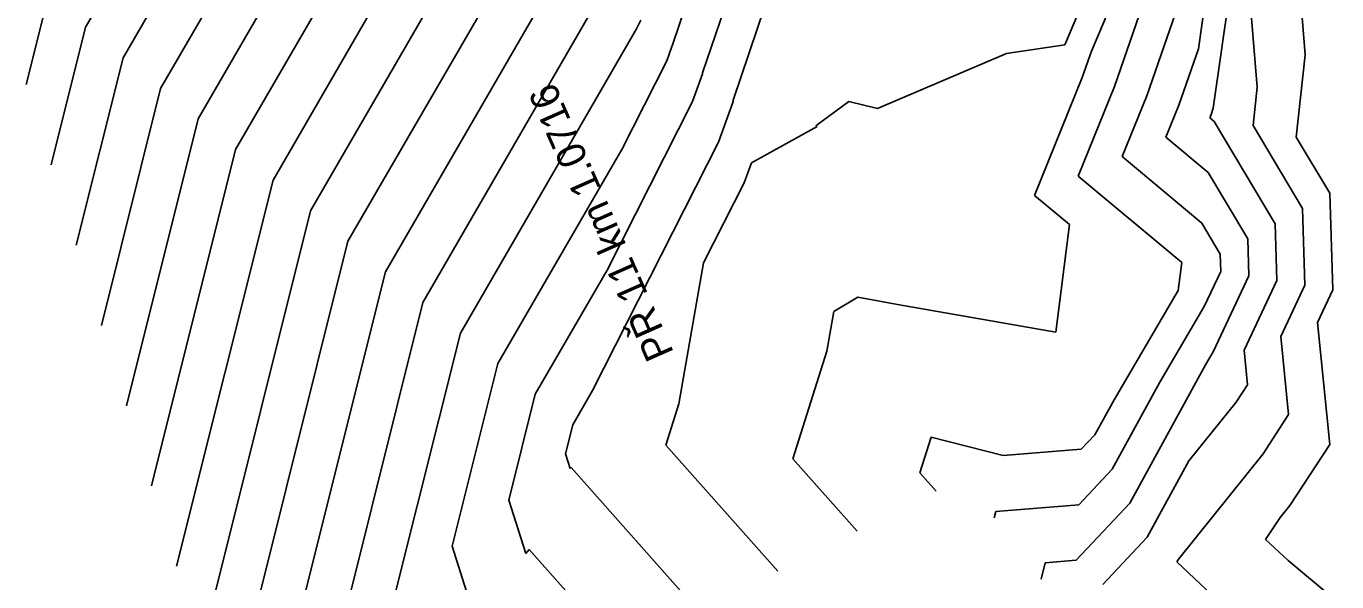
# Model space of a CAD drawing. Extents: x -549394 to -546608, y -1037055 to -1033629.
# Drawn here: x -547337.7 to -546924.3, y -1036782.7 to -1036607.7 of the extents above; entities that cross this region are included whole.
import ezdxf

# ---------------------------------------------------------------- set-up
doc = ezdxf.new("R2010")
doc.units = 0
for name, color, linetype in [('hlavni_vrst', 7, 'Continuous'), ('norm_vrst', 7, 'Continuous'), ('x_popis_pricne_rezy_C31', 7, 'Continuous')]:
    doc.layers.add(name, color=color, linetype=linetype)

msp = doc.modelspace()

# ---------------------------------------------------------------- linework, layer by layer
at = {"layer": 'hlavni_vrst'}
for p, q in [((-547307.11, -1036617.61), (-547290.03, -1036588.14)), ((-546994.44, -1036626.7), (-546982.33, -1036591.7)), ((-546934.27, -1036616.63), (-546936.34, -1036592.46)), ((-547248.03, -1036665.8), (-547208.29, -1036597.26)), ((-547134, -1036613.83), (-547129.38, -1036600.2)), ((-547135.66, -1036618.58), (-547134.01, -1036614.01)), ((-547134.01, -1036614.01), (-547134, -1036613.83)), ((-547321.87, -1036676.65), (-547307.11, -1036617.61)), ((-547149.83, -1036646.52), (-547135.66, -1036618.58)), ((-546937.13, -1036642.58), (-546934.27, -1036616.63)), ((-547005.86, -1036654.86), (-546994.44, -1036626.7)), ((-546926.57, -1036660.32), (-546937.13, -1036642.58)), ((-547188.94, -1036714), (-547149.83, -1036646.52)), ((-546973.19, -1036682.1), (-547005.86, -1036654.86)), ((-546925.59, -1036690.71), (-546926.57, -1036660.32)), ((-547282.37, -1036803.14), (-547248.03, -1036665.8)), ((-546974.33, -1036690.95), (-546973.19, -1036682.1)), ((-546994.58, -1036725.38), (-546974.33, -1036690.95)), ((-546930.45, -1036701.02), (-546925.59, -1036690.71)), ((-546926.57, -1036739.43), (-546930.45, -1036701.02)), ((-547203.33, -1036771.52), (-547188.94, -1036714)), ((-547000.65, -1036736.43), (-546994.58, -1036725.38)), ((-547055.8, -1036748.38), (-547052.27, -1036737.18)), ((-547052.27, -1036737.18), (-547029.57, -1036742.95)), ((-547004.93, -1036741), (-547000.65, -1036736.43)), ((-547029.57, -1036742.95), (-547004.93, -1036741)), ((-546939.15, -1036758.68), (-546926.57, -1036739.43)), ((-547050.66, -1036754.16), (-547055.8, -1036748.38)), ((-546942.21, -1036762.49), (-546939.15, -1036758.68)), ((-546946.78, -1036769.4), (-546942.21, -1036762.49)), ((-547194.12, -1036800.51), (-547203.33, -1036771.52)), ((-546939.65, -1036776.06), (-546946.78, -1036769.4)), ((-546916.57, -1036795.26), (-546939.65, -1036776.06))]:
    msp.add_line(p, q, dxfattribs=at)
at = {"layer": 'norm_vrst'}
for p, q in [((-547010.16, -1036613.49), (-546995.25, -1036578.44)), ((-547001.73, -1036615.51), (-546986.91, -1036580.65)), ((-547318.93, -1036607.97), (-547306.38, -1036586.32)), ((-547295.29, -1036627.25), (-547273.68, -1036589.97)), ((-546967.98, -1036614.76), (-546963.87, -1036586.17)), ((-546963.31, -1036633.53), (-546956.72, -1036587.72)), ((-547283.48, -1036636.89), (-547257.33, -1036591.79)), ((-547271.66, -1036646.53), (-547240.99, -1036593.61)), ((-547337.68, -1036626.05), (-547330.74, -1036598.33)), ((-547259.84, -1036656.17), (-547224.64, -1036595.44)), ((-547124.36, -1036622.38), (-547115.59, -1036596.46)), ((-546984.28, -1036629.61), (-546972.65, -1036595.99)), ((-547236.21, -1036675.44), (-547191.94, -1036599.08)), ((-547224.39, -1036685.08), (-547175.6, -1036600.9)), ((-547114.72, -1036630.92), (-547104.53, -1036600.82)), ((-546949.42, -1036626.82), (-546951.49, -1036602.61)), ((-547212.58, -1036694.72), (-547159.25, -1036602.73)), ((-547145.21, -1036608.53), (-547143.8, -1036605.76)), ((-547329.77, -1036651.35), (-547318.93, -1036607.97)), ((-547200.76, -1036704.36), (-547145.21, -1036608.53)), ((-547028.47, -1036616.27), (-547010.16, -1036613.49)), ((-546974.13, -1036632.52), (-546967.98, -1036614.76)), ((-547069.17, -1036633.54), (-547028.47, -1036616.27)), ((-547004.6, -1036623.79), (-547001.73, -1036615.51)), ((-547127.52, -1036631.39), (-547124.37, -1036622.71)), ((-547124.37, -1036622.71), (-547124.36, -1036622.38)), ((-547313.97, -1036701.95), (-547295.29, -1036627.25)), ((-547019.68, -1036660.98), (-547004.6, -1036623.79)), ((-546950.76, -1036638.96), (-546949.42, -1036626.82)), ((-547154.45, -1036684.51), (-547127.52, -1036631.39)), ((-547119.37, -1036644.21), (-547114.74, -1036631.41)), ((-547114.74, -1036631.41), (-547114.72, -1036630.92)), ((-547088.63, -1036639.03), (-547078.28, -1036631.42)), ((-547078.28, -1036631.42), (-547069.17, -1036633.54)), ((-546992.05, -1036648.75), (-546984.28, -1036629.61)), ((-546978.23, -1036642.63), (-546974.13, -1036632.52)), ((-546964.41, -1036636.51), (-546963.97, -1036635.43)), ((-546963.97, -1036635.43), (-546963.31, -1036633.53)), ((-547306.07, -1036727.25), (-547283.48, -1036636.89)), ((-547108.94, -1036650.7), (-547088.21, -1036639.28)), ((-547088.21, -1036639.28), (-547088.63, -1036639.03)), ((-546962.98, -1036637.7), (-546964.41, -1036636.51)), ((-546943.82, -1036669.9), (-546962.98, -1036637.7)), ((-546935.2, -1036665.11), (-546950.76, -1036638.96)), ((-546964.93, -1036653.71), (-546978.23, -1036642.63)), ((-547298.17, -1036752.54), (-547271.66, -1036646.53)), ((-547159.06, -1036722.5), (-547119.37, -1036644.21)), ((-547111.23, -1036657.03), (-547108.94, -1036650.7)), ((-546966.88, -1036669.72), (-546992.05, -1036648.75)), ((-547290.27, -1036777.84), (-547259.84, -1036656.17)), ((-546952.45, -1036674.69), (-546964.93, -1036653.71)), ((-547124.03, -1036682.27), (-547111.23, -1036657.03)), ((-547008.65, -1036670.18), (-547019.68, -1036660.98)), ((-546934.42, -1036689.26), (-546935.2, -1036665.11)), ((-547013, -1036704.05), (-547008.65, -1036670.18)), ((-546961.08, -1036679.48), (-546966.88, -1036669.72)), ((-546943.25, -1036687.81), (-546943.82, -1036669.9)), ((-547274.47, -1036828.44), (-547236.21, -1036675.44)), ((-546952.07, -1036686.36), (-546952.45, -1036674.69)), ((-546960.9, -1036684.91), (-546961.08, -1036679.48)), ((-547256.91, -1036815.11), (-547224.39, -1036685.08)), ((-547177.13, -1036723.64), (-547154.45, -1036684.51)), ((-547131.88, -1036726.67), (-547124.03, -1036682.27)), ((-546966.13, -1036696.03), (-546960.9, -1036684.91)), ((-546963.31, -1036710.25), (-546952.07, -1036686.36)), ((-546953.58, -1036709.78), (-546943.25, -1036687.81)), ((-546942.01, -1036705.4), (-546934.42, -1036689.26)), ((-547082.98, -1036697.51), (-547075.38, -1036693.06)), ((-547075.38, -1036693.06), (-547062.87, -1036695.33)), ((-547239.05, -1036800.58), (-547212.58, -1036694.72)), ((-547085.21, -1036710.11), (-547082.98, -1036697.51)), ((-547062.87, -1036695.33), (-547013, -1036704.05)), ((-546980.16, -1036719.88), (-546966.13, -1036696.03)), ((-547221.19, -1036786.05), (-547200.76, -1036704.36)), ((-546939.53, -1036730.04), (-546942.01, -1036705.4)), ((-547095.88, -1036744.02), (-547085.21, -1036710.11)), ((-546952.48, -1036720.66), (-546953.58, -1036709.78)), ((-546965.75, -1036714.39), (-546963.31, -1036710.25)), ((-546989.66, -1036757.97), (-546965.75, -1036714.39)), ((-547165.31, -1036733.28), (-547159.06, -1036722.5)), ((-546995.15, -1036747.2), (-546980.16, -1036719.88)), ((-546956.05, -1036726.11), (-546952.48, -1036720.66)), ((-547185.47, -1036756.99), (-547177.13, -1036723.64)), ((-546970.96, -1036744.66), (-546956.05, -1036726.11)), ((-547135.97, -1036739.65), (-547131.88, -1036726.67)), ((-546947.6, -1036742.39), (-546939.53, -1036730.04)), ((-547167.61, -1036742.46), (-547165.31, -1036733.28)), ((-547166.14, -1036747.09), (-547167.61, -1036742.46)), ((-547100.59, -1036779.43), (-547135.97, -1036739.65)), ((-546974.18, -1036775.46), (-546947.6, -1036742.39)), ((-547165.85, -1036746.75), (-547166.14, -1036747.09)), ((-547125.55, -1036792.06), (-547165.85, -1036746.75)), ((-547075.62, -1036766.8), (-547095.88, -1036744.02)), ((-547005.73, -1036758.48), (-546995.15, -1036747.2)), ((-546984.17, -1036768.73), (-546970.96, -1036744.66)), ((-547180.13, -1036773.8), (-547185.47, -1036756.99)), ((-547031.9, -1036760.56), (-547005.73, -1036758.48)), ((-547006.54, -1036775.97), (-546989.66, -1036757.97)), ((-547032.39, -1036762.59), (-547031.9, -1036760.56)), ((-546998.11, -1036783.6), (-546984.17, -1036768.73)), ((-547179.1, -1036772.55), (-547180.13, -1036773.8)), ((-547150.52, -1036804.69), (-547179.1, -1036772.55)), ((-547016.35, -1036776.75), (-547006.54, -1036775.97)), ((-546974.84, -1036776.47), (-546974.18, -1036775.46)), ((-547017.57, -1036781.87), (-547016.35, -1036776.75)), ((-546941.33, -1036807.81), (-546974.84, -1036776.47))]:
    msp.add_line(p, q, dxfattribs=at)

# ---------------------------------------------------------------- texts
at = {"layer": 'x_popis_pricne_rezy_C31'}
msp.add_text('PŘ 11 km 1.0716', height=9.0627, rotation=113.8678, dxfattribs=at).set_placement((-547133.31, -1036710.58))

doc.saveas('drawing.dxf')
